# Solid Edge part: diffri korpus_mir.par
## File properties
Author: Türk
Template: Iso Part.par
Last saved by: Türk
Revision: 3
Application: Solid Edge
Accuracy: 0,990
Username: Türk
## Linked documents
diffri korpus.par
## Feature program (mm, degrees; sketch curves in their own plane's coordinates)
part copy "CopiedPart_1"
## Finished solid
Body 1: solid body, 75 faces, 217 edges, 140 vertices.
  Faces by surface: plane 52, cylinder 23
  Edges by curve: line 143, circle 56, ellipse 16, intersection 2
Bounding box of the edges (mm): 315.000 x 115.000 x 267.500, from (-157.5, -115, -105) to (157.5, 0, 162.5).
Cylindrical faces by radius (mm): R25 x4, R27.5 x3, R40 x4, R50 x4, R52.5 x3, R100 x4, R102.5 x1
Planar faces by outward normal: +x 9, +y 4, +z 11, -x 10, -y 2, -z 8, oblique 8
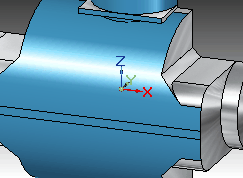
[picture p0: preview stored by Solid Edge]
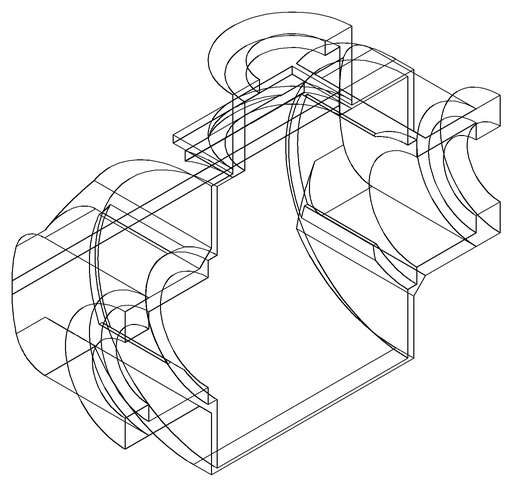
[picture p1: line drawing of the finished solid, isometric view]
